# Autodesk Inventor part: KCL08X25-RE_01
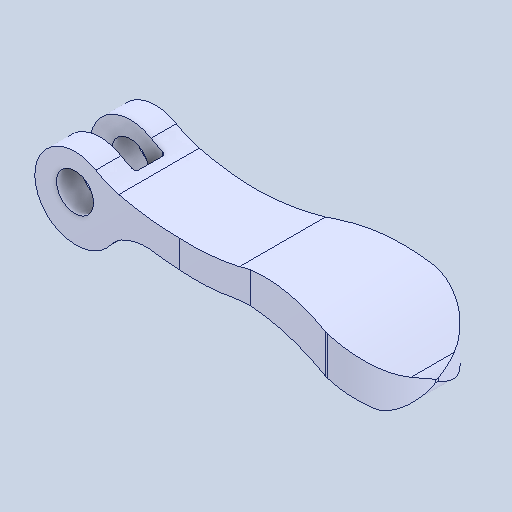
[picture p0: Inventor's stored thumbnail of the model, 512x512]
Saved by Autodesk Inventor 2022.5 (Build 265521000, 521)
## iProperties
Created: 2024-08
Part Number: KCL08X25-RE_01
Material: 一般
Document SubType Name: Modeling
Designer: ImaoCorp
Density: 1 g/cm^3
Appearance: 既定
Author: ImaoCorp
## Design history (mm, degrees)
feature "KCL08X25-RE_01"
node "ソリッド1"
